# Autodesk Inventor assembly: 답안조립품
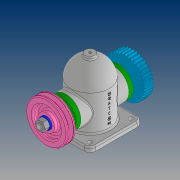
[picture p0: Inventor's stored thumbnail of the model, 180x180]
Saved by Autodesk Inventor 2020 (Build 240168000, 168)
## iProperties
Created: 2021-08
Part Number: 답안조립품
Document SubType Name: Assembly
Designer: PC312-
Author: PC312-
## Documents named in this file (14)
- C:\Users\PC312-\Desktop\710809V1005\답안조립품.iam
- C:\Users\PC312-\Desktop\710809V1005\본체.ipt
- C:\Users\PC312-\Desktop\710809V1005\축.ipt
- C:\Users\PC312-\Desktop\710809V1005\베어링 6203.ipt
- C:\Users\PC312-\Desktop\710809V1005\부시.ipt
- C:\Users\PC312-\Desktop\710809V1005\커버.ipt
- C:\Users\PC312-\Desktop\710809V1005\오일 실 26 38 8.ipt
- C:\Users\PC312-\Desktop\710809V1005\볼트 M4.ipt
- C:\Users\PC312-\Desktop\710809V1005\키 5x5x12.ipt
- C:\Users\PC312-\Desktop\710809V1005\V-벨트풀리.ipt
- V-벨트풀리.ipt
- C:\Users\PC312-\Desktop\710809V1005\스퍼기어.ipt
- C:\Users\PC312-\Desktop\710809V1005\와셔 12x24.ipt
- C:\Users\PC312-\Desktop\710809V1005\너트 M12x1.25.ipt
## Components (1 placed, 1 different names)
1. V-벨트풀리:1
